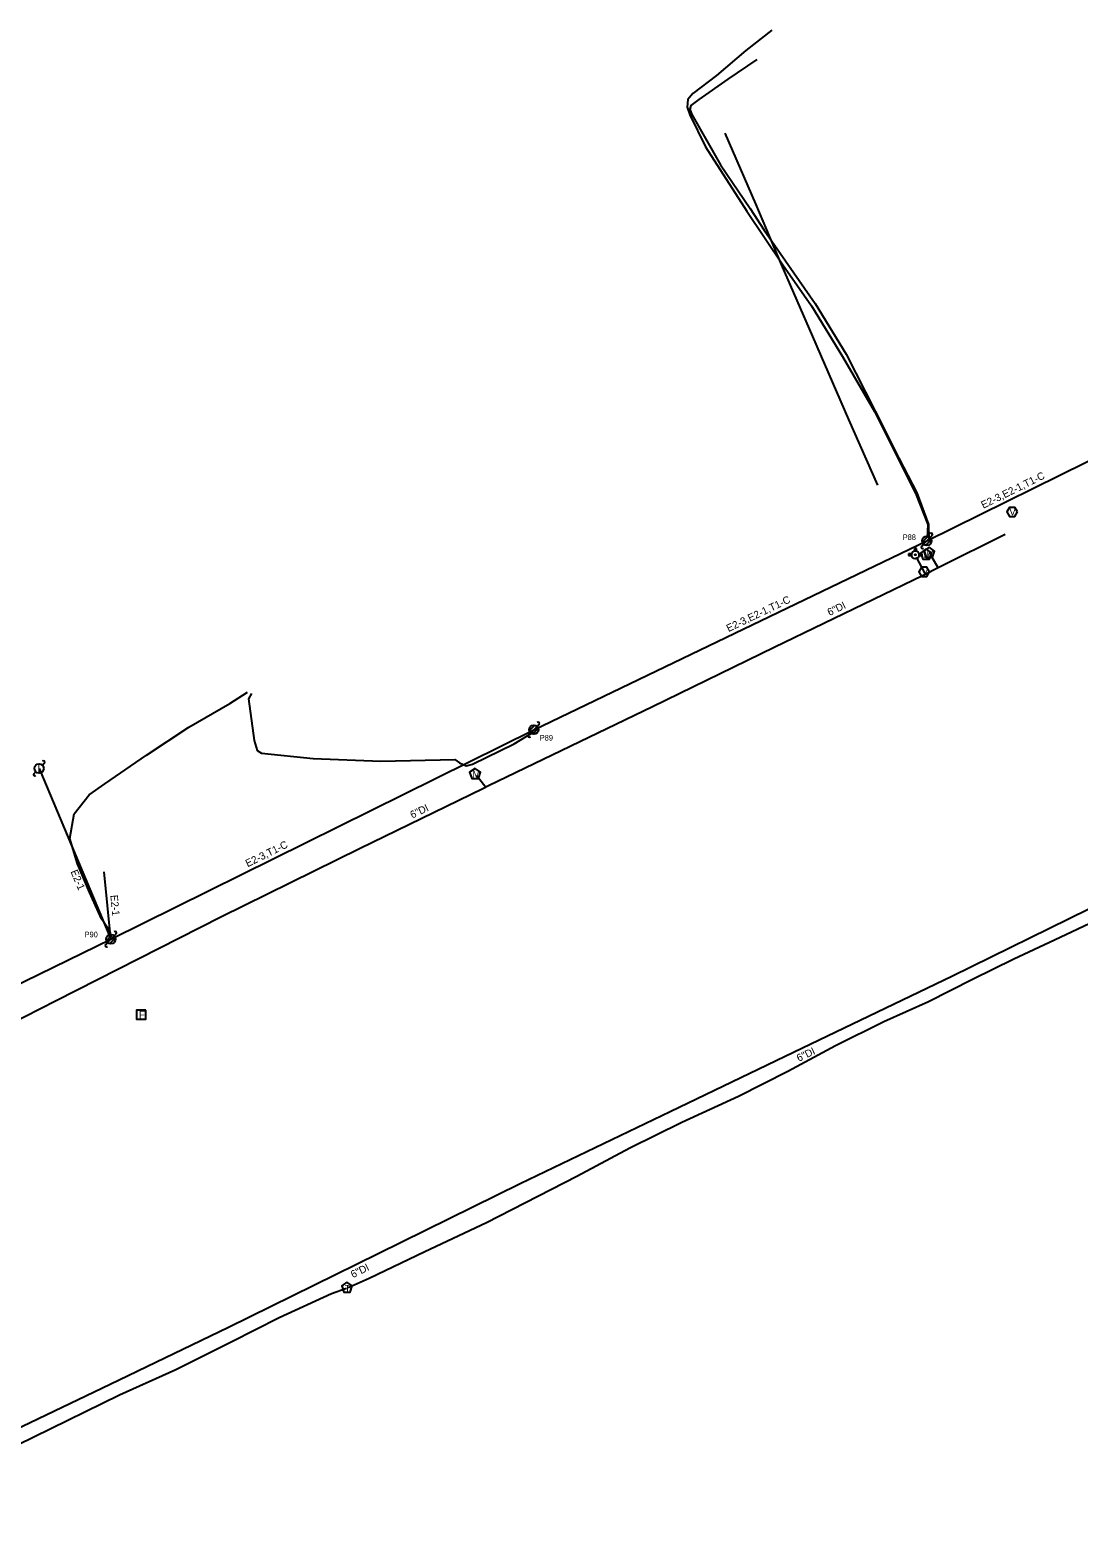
# Model space of a CAD drawing. Extents: x 1741604 to 1825760, y 1164229 to 1194908.
# Drawn here: x 1756379 to 1756945, y 1169455 to 1170268 of the extents above; entities that cross this region are included whole.
import ezdxf

# ---------------------------------------------------------------- set-up
doc = ezdxf.new("R2010")
doc.units = 0
for name, color, linetype in [('RD_EX_SU_Elec', 7, 'Continuous'), ('RD_EX_SU_H2O', 7, 'Continuous'), ('RD_EX_SU_Ovhd', 7, 'Continuous'), ('RD_EX_SU_Pole', 7, 'Continuous'), ('RD_EX_SU_Telecom', 7, 'Continuous'), ('RD_EX_SU_TX_H2O', 7, 'Continuous'), ('RD_EX_SU_TX_Pole', 7, 'Continuous')]:
    doc.layers.add(name, color=color, linetype=linetype)

msp = doc.modelspace()

# ---------------------------------------------------------------- linework, layer by layer
at = {"layer": 'RD_EX_SU_Elec'}
for points in [[(1756771.11, 1170252.61), (1756755.48, 1170242), (1756739.77, 1170231.07), (1756735.56, 1170227.95), (1756734.94, 1170225.88), (1756736.04, 1170222.98), (1756751.48, 1170195.87), (1756767.52, 1170172.36), (1756775.05, 1170160.66), (1756802.6, 1170121.09), (1756819.27, 1170093.74), (1756834.81, 1170063.03), (1756847.68, 1170037.68), (1756857.43, 1170018.97), (1756863.7, 1170001.96), (1756863.9, 1169994.38)], [(1756753.92, 1170212.88), (1756770.37, 1170174.92), (1756784.17, 1170142.19), (1756801.07, 1170103.29), (1756820.47, 1170058.5), (1756836.05, 1170023.1)], [(1756498.71, 1169910.78), (1756497.09, 1169907.85), (1756500.14, 1169885.37), (1756501.7, 1169880.07), (1756504.13, 1169878.54), (1756531.84, 1169875.76), (1756568.48, 1169874.38), (1756608.21, 1169875.14), (1756610.72, 1169873.46), (1756614.35, 1169871.77), (1756617.85, 1169872.72), (1756640.28, 1169883.59), (1756650.91, 1169890.08)]]:
    msp.add_lwpolyline(points, dxfattribs=at)
at = {"layer": 'RD_EX_SU_H2O'}
for p, q in [((1756854.52, 1169986.18), (1756852.88, 1169986.18)), ((1756852.88, 1169986.18), (1756852.88, 1169985.13)), ((1756852.88, 1169985.13), (1756854.48, 1169985.13)), ((1756856.05, 1169988.96), (1756856.05, 1169987.62)), ((1756857.1, 1169988.96), (1756856.05, 1169988.96)), ((1756856.95, 1169984.38), (1756861.79, 1169975.16)), ((1756857.1, 1169987.6), (1756857.1, 1169988.96)), ((1756860.23, 1169986.18), (1756858.54, 1169986.18)), ((1756858.58, 1169985.13), (1756860.23, 1169985.13)), ((1756860.23, 1169985.13), (1756860.23, 1169986.18)), ((1756864.65, 1169985.49), (1756868.7, 1169978.72)), ((1756619.99, 1169866.72), (1756624.92, 1169860.32))]:
    msp.add_line(p, q, dxfattribs=at)
for points in [[(1756911.59, 1170008.67), (1756910.15, 1170011.17), (1756907.26, 1170011.17), (1756905.82, 1170008.67), (1756907.26, 1170006.17), (1756910.15, 1170006.17)], [(1756862.31, 1169988.81), (1756859.41, 1169986.7), (1756860.52, 1169983.29), (1756864.1, 1169983.29), (1756865.21, 1169986.7)], [(1756863.98, 1169989.73), (1756861.07, 1169987.63), (1756862.18, 1169984.22), (1756865.77, 1169984.22), (1756866.88, 1169987.63)], [(1756864.13, 1169976.4), (1756862.68, 1169978.9), (1756859.8, 1169978.9), (1756858.35, 1169976.4), (1756859.8, 1169973.9), (1756862.68, 1169973.9)], [(1756619.18, 1169870.42), (1756616.28, 1169868.32), (1756617.39, 1169864.91), (1756620.98, 1169864.91), (1756622.08, 1169868.32)]]:
    msp.add_lwpolyline(points, close=True, dxfattribs=at)
for points in [[(1755923.91, 1169771.92), (1755939.52, 1169740.59), (1755963.83, 1169686.41), (1755992.89, 1169612.51), (1756007.59, 1169575.08), (1756015.28, 1169564.93), (1756064.58, 1169585.92), (1756121.11, 1169611.4), (1756206.64, 1169653.11), (1756271, 1169684.14), (1756275.23, 1169686.24), (1756334.12, 1169715.1), (1756393.44, 1169745.19), (1756482.23, 1169790.32), (1756557.26, 1169827.38), (1756623.37, 1169859.51), (1756626.48, 1169861.14), (1756714.89, 1169903.8), (1756780.35, 1169935.86), (1756860.71, 1169974.61), (1756869.54, 1169979.15), (1756904.9, 1169996.7)], [(1756238.45, 1169448.31), (1756289.53, 1169473.78), (1756361.95, 1169509.43), (1756422.41, 1169538.26), (1756486.25, 1169569.02), (1756566.97, 1169608.84), (1756643.55, 1169646.48), (1756724.44, 1169685.4), (1756795.74, 1169719.73), (1756876.22, 1169758.33), (1756950.1, 1169794.65)]]:
    msp.add_lwpolyline(points, dxfattribs=at)
for radius in [2.1, 0.263]:
    msp.add_circle((1756856.53, 1169985.58), radius, dxfattribs=at)
for start, end in [(163.3387, 192.31502), (74.24552, 103.21276), (347.68498, 16.6613)]:
    msp.add_arc((1756856.53, 1169985.58), 2.1, start, end, dxfattribs=at)
at = {"layer": 'RD_EX_SU_Ovhd'}
for p, q in [((1756862.78, 1169993.13), (1757034.42, 1170077.95)), ((1756650.82, 1169891.28), (1756862.78, 1169993.13)), ((1756422.89, 1169778.33), (1756650.82, 1169891.28)), ((1756384.15, 1169870.36), (1756422.89, 1169778.33)), ((1756422.89, 1169778.33), (1756419.33, 1169814.61)), ((1756250.77, 1169694.49), (1756422.89, 1169778.33))]:
    msp.add_line(p, q, dxfattribs=at)
at = {"layer": 'RD_EX_SU_Pole'}
for p, q in [((1756859.95, 1169990.3), (1756861.01, 1169991.36)), ((1756860.37, 1169992.49), (1756863.43, 1169995.55)), ((1756861.01, 1169991.36), (1756864.55, 1169994.9)), ((1756862.13, 1169990.72), (1756865.2, 1169993.78)), ((1756864.55, 1169994.9), (1756865.61, 1169995.96)), ((1756648.4, 1169890.63), (1756651.46, 1169893.7)), ((1756649.05, 1169889.51), (1756652.59, 1169893.05)), ((1756652.59, 1169893.05), (1756653.65, 1169894.11)), ((1756647.99, 1169888.45), (1756649.05, 1169889.51)), ((1756650.17, 1169888.87), (1756653.23, 1169891.93)), ((1756381.32, 1169867.54), (1756382.38, 1169868.6)), ((1756385.92, 1169872.13), (1756386.98, 1169873.19)), ((1756420.48, 1169777.68), (1756423.54, 1169780.74)), ((1756421.12, 1169776.56), (1756424.66, 1169780.1)), ((1756424.66, 1169780.1), (1756425.72, 1169781.16)), ((1756420.06, 1169775.5), (1756421.12, 1169776.56)), ((1756422.25, 1169775.91), (1756425.31, 1169778.98))]:
    msp.add_line(p, q, dxfattribs=at)
for centre in [(1756862.78, 1169993.13), (1756650.82, 1169891.28), (1756384.15, 1169870.36), (1756422.89, 1169778.33)]:
    msp.add_circle(centre, 2.5, dxfattribs=at)
for centre, start, end in [((1756865.08, 1169996.49), 315, 135), ((1756860.48, 1169989.77), 135, 315), ((1756653.12, 1169894.64), 315, 135), ((1756648.52, 1169887.92), 135, 315), ((1756386.45, 1169873.72), 315, 135), ((1756381.85, 1169867.01), 135, 315), ((1756425.19, 1169781.69), 315, 135), ((1756420.59, 1169774.97), 135, 315)]:
    msp.add_arc(centre, 0.75, start, end, dxfattribs=at)
at = {"layer": 'RD_EX_SU_Telecom'}
for points in [[(1756779.16, 1170268.5), (1756765.14, 1170257.53), (1756749.37, 1170244.09), (1756736.67, 1170234.4), (1756733.85, 1170231.13), (1756733.61, 1170227.04), (1756734.89, 1170222.75), (1756743.41, 1170205.63), (1756765.7, 1170170.84), (1756785.1, 1170141.93), (1756800.5, 1170119.79), (1756817.32, 1170092.44), (1756834.47, 1170062.9), (1756847.16, 1170037.66), (1756856.63, 1170018.8), (1756863.22, 1170001.89), (1756862.93, 1169994.81)], [(1756423.22, 1169779.35), (1756422.48, 1169782.27), (1756417.74, 1169789.29), (1756411.36, 1169803.65), (1756404.91, 1169818.92), (1756400.82, 1169832.52), (1756403.12, 1169845.9), (1756411.09, 1169856.17), (1756419.67, 1169862.09), (1756442.14, 1169877.46), (1756464.98, 1169892.69), (1756487.05, 1169905.37), (1756496.44, 1169911.45)], [(1756550.82, 1169590.44), (1756562.08, 1169595.47), (1756592.2, 1169609.85), (1756625.33, 1169625.46), (1756674.12, 1169650.52), (1756702.57, 1169665.75), (1756730.66, 1169679.55), (1756761.28, 1169693.68), (1756787.78, 1169707.05), (1756813.47, 1169720.94), (1756839.47, 1169733.91), (1756863.61, 1169744.63), (1756887.27, 1169756.75), (1756909.64, 1169767.76), (1756931.59, 1169777.98), (1756956.76, 1169789.88)], [(1756549.94, 1169589.96), (1756541.82, 1169587), (1756513.59, 1169574.05), (1756488.12, 1169561.24), (1756457.84, 1169546.06), (1756427.48, 1169532.35), (1756381.3, 1169509.82), (1756347.29, 1169493.22), (1756314.45, 1169477.96), (1756280.78, 1169460.79), (1756237.9, 1169434.39), (1756215.68, 1169416.31), (1756197.86, 1169399.08), (1756179.37, 1169372.51), (1756168.44, 1169336.07), (1756173.6, 1169292.17), (1756175.56, 1169279.77)]]:
    msp.add_lwpolyline(points, dxfattribs=at)
for points in [[(1756441.74, 1169740.11), (1756436.74, 1169740.11), (1756436.74, 1169735.11), (1756441.74, 1169735.11)], [(1756550.15, 1169593.39), (1756547.3, 1169591.32), (1756548.39, 1169587.96), (1756551.91, 1169587.96), (1756553, 1169591.32)]]:
    msp.add_lwpolyline(points, close=True, dxfattribs=at)

# ---------------------------------------------------------------- texts
at = {"layer": 'RD_EX_SU_H2O'}
for s, p in [('V', (1756907.27, 1170006.79)), ('M', (1756860.94, 1169983.77)), ('M', (1756862.61, 1169984.69)), ('V', (1756860.03, 1169974.52)), ('M', (1756617.81, 1169865.38))]:
    msp.add_text(s, height=3.75, dxfattribs=at).set_placement(p)
at = {"layer": 'RD_EX_SU_Ovhd'}
for s, rotation, p in [('E2-3,E2-1,T1-C', 26.29768, (1756893.16, 1170010.38)), ('E2-3,E2-1,T1-C', 25.66484, (1756755.84, 1169943.88)), ('E2-3,T1-C', 26.36128, (1756496.59, 1169817.08)), ('E2-1', 292.82992, (1756401.05, 1169814.75)), ('E2-1', 275.60647, (1756422.58, 1169801.97))]:
    msp.add_text(s, height=4, rotation=rotation, dxfattribs=at).set_placement(p)
at = {"layer": 'RD_EX_SU_Pole'}
msp.add_text('L', height=4, dxfattribs=at).set_placement((1756383.29, 1169868.36))
at = {"layer": 'RD_EX_SU_Telecom'}
for s, height, p in [('F', 4, (1756437.99, 1169735.61)), ('T', 3.75, (1756548.92, 1169588.16))]:
    msp.add_text(s, height=height, dxfattribs=at).set_placement(p)
at = {"layer": 'RD_EX_SU_TX_H2O'}
for rotation, p in [(25.74611, (1756810.28, 1169952.51)), (25.91361, (1756585.38, 1169843.27)), (25.62391, (1756793.74, 1169712.12)), (26.25846, (1756553.38, 1169595.45))]:
    msp.add_text('6"DI', height=4, rotation=rotation, dxfattribs=at).set_placement(p)
at = {"layer": 'RD_EX_SU_TX_Pole'}
for s, p in [('P88', (1756849.71, 1169993.58)), ('P89', (1756654.05, 1169885.4)), ('P90', (1756408.69, 1169779.33))]:
    msp.add_text(s, height=3, dxfattribs=at).set_placement(p)

doc.saveas('drawing.dxf')
